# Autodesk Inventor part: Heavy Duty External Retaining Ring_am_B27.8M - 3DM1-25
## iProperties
Shininess: 64.0
Length Units: 11269
Angle Units: 11279
Time Units: 11290
Mass Units: 11283
Length Display Precision: 3
Angle Display Precision: 2
Compacted: True
Part Number: Heavy Duty External Retaining Ring_am_B27.8M - 3DM1-25
Document SubType Name: Modeling
Created: 2006-11
Material: Par défaut
Designer: profs_sti
Density: 0.0
Volumn: 0.0
Area: 0.0
PropertySet Name: Model Information
Control State: 0
Master: False
Checked Out: False
Author: profs_sti
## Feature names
1. Base1
